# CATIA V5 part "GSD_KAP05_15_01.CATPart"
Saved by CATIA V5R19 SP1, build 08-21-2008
Part number: GSD_HELIX_01
Definition: Beispielmodell für die Funktion Helix.
Description: CATIA V5 Flächenmodellierung  Copyright (c) 2009 Maik Hertha IT Consultants
Bounding box of the stored display mesh (mm): x 20 to 20, y 0 to 15, z 0 to 20
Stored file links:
  C:\Users\Maik\CAD Daten\modelle\gsd_buch_uebung\GSD_KAP05_15_01.CATPart
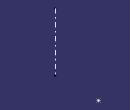
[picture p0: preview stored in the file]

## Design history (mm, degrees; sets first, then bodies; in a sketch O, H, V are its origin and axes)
AxisSystem1: origin (0, 0, 0), X (1, 0, 0), Y (0, 1, 0), Z (0, 0, 1)
Set1
  Plane1: type Equation, A 1, B 0, C 0, RefAxis AxisSystem1, Length 20
  Sketch1 on Plane1, origin (20, 0, 0), H (0, 1, 0), V (0, 0, 1)
    line L1 (0, 20) -> (0, 0)
    point P1 (0, 20)
    point P2 (0, 0)
    construction line L2 (-12.788, 0) -> (17.6565, 0)
    point P3 (-12.788, 0)
    distance L2 P2 = 0
    distance P2 P1 = 20 {= Sketch1.distance(L2 P2) + 20mm}
    coincidence: P1 V, P3 H
    vertical: L1 V
    horizontal: L2 H
  Plane2: type Normal, Curve Sketch1, RefPoint {point type OnCurve, Support Sketch1, Ratio 1}
  Intersect1: ToIntersect1 Plane1, ToIntersect2 Plane2
  Point1: type OnCurve, Support Intersect1, Length 15
Set2 "Helix Normal"
  Point2: linked copy from another document
  Sketch2, origin (20, 0, 0), H (0, 1, 0), V (0, 0, 1), geometry linked from another document
Set3 "Helix Profile"
  Point3: linked copy from another document
  Sketch3, origin (20, 0, 0), H (0, 1, 0), V (0, 0, 1), geometry linked from another document
  Sketch4 on Plane1, origin (20, 0, 0), H (0, 1, 0), V (0, 0, 1)
    arc A1 centre (-3.1166, 8.4729) radius 20 from (14.0242, -1.8321) to (12.2162, 21.3145) ccw
    reference projected point E1 (15, 0) from Point3
    radius A1 = 20
    coincidence: E1 A1
Body1 (main body)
